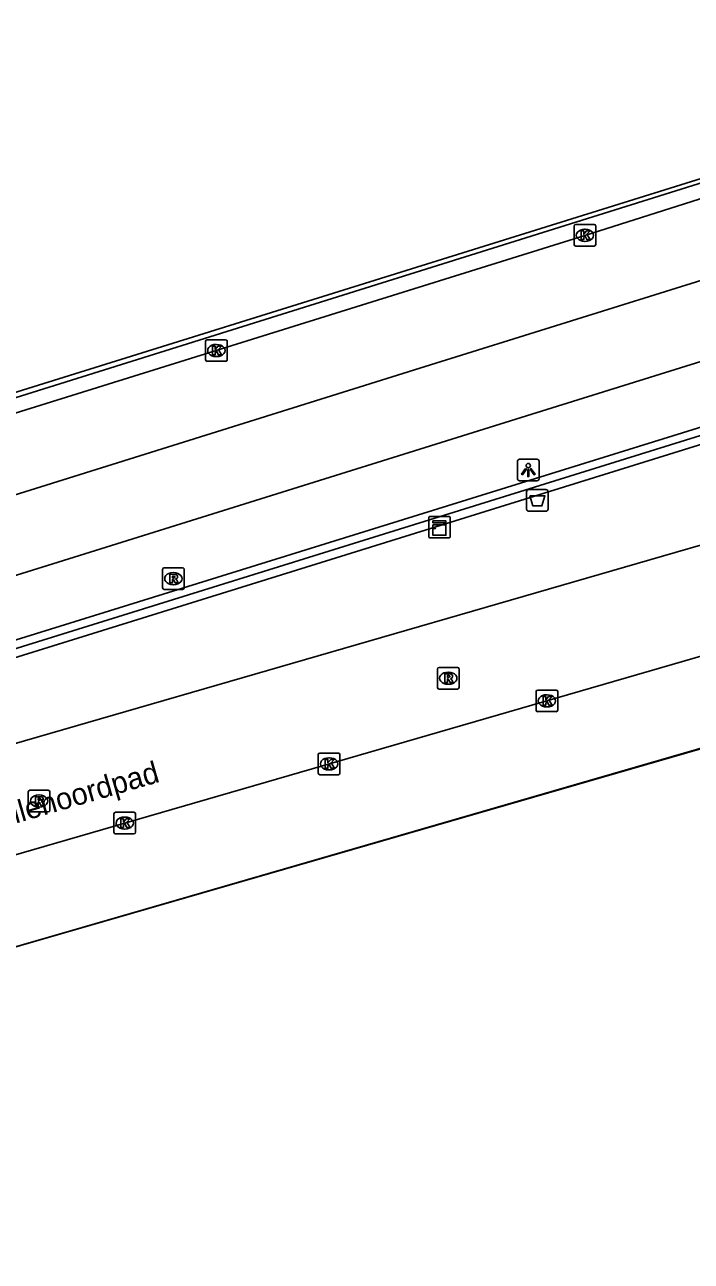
# Model space of a CAD drawing. Extents: x 160806 to 161707, y 383697 to 384148.
# Drawn here: x 161174.1 to 161204.9, y 383814.4 to 383871.5 of the extents above; entities that cross this region are included whole.
import ezdxf

# ---------------------------------------------------------------- set-up
doc = ezdxf.new("R2010")
doc.units = 0
for name, color, linetype in [('IMGEO_Afvalbak', 7, 'Continuous'), ('IMGEO_Fietspad_open', 7, 'Continuous'), ('IMGEO_Hek', 7, 'Continuous'), ('IMGEO_Kast', 7, 'Continuous'), ('IMGEO_Kolk', 7, 'Continuous'), ('IMGEO_Lichtpunt', 7, 'Continuous'), ('IMGEO_Muur', 7, 'Continuous'), ('IMGEO_Openbare_ruimte_label', 7, 'Continuous'), ('IMGEO_OVBaan_gesloten', 7, 'Continuous'), ('IMGEO_Pand', 7, 'Continuous'), ('IMGEO_Pand_overbouw', 7, 'Continuous'), ('IMGEO_Rioolput', 7, 'Continuous'), ('IMGEO_Voetpad_open', 7, 'Continuous')]:
    doc.layers.add(name, color=color, linetype=linetype)

msp = doc.modelspace()

# ---------------------------------------------------------------- linework, layer by layer
at = {"layer": 'IMGEO_Afvalbak'}
for p, q in [((161197.301, 383849.162), (161197.301, 383849.962)), ((161197.301, 383849.962), (161197.301, 383849.162)), ((161197.401, 383850.062), (161198.191, 383850.062)), ((161198.191, 383850.062), (161197.401, 383850.062)), ((161198.291, 383849.962), (161198.291, 383849.162)), ((161198.291, 383849.162), (161198.291, 383849.962)), ((161198.191, 383849.062), (161197.401, 383849.062)), ((161197.401, 383849.062), (161198.191, 383849.062))]:
    msp.add_line(p, q, dxfattribs=at)
msp.add_lwpolyline([(161197.444, 383849.776), (161198.148, 383849.776), (161197.999, 383849.306), (161197.593, 383849.306), (161197.444, 383849.776)], dxfattribs=at)
for centre, start, end in [((161197.401, 383849.962), 90, 180), ((161197.401, 383849.962), 90, 180), ((161198.191, 383849.962), 0, 90), ((161198.191, 383849.962), 360, 90), ((161197.401, 383849.162), 180, 270), ((161197.401, 383849.162), 180, 270), ((161198.191, 383849.162), 270, 0), ((161198.191, 383849.162), 270, 0)]:
    msp.add_arc(centre, 0.1, start, end, dxfattribs=at)
at = {"layer": 'IMGEO_Fietspad_open'}
for points in [[(161233.944, 383854.997), (161230.53, 383854.241), (161222.537, 383852.474), (161163.411, 383835.363), (161161.786, 383834.896)], [(161159.382, 383829.051), (161223.387, 383847.584)]]:
    msp.add_lwpolyline(points, dxfattribs=at)
at = {"layer": 'IMGEO_Hek'}
msp.add_lwpolyline([(161215.707, 383880.868), (161206.505, 383864.592), (161170.587, 383853.341), (161164.694, 383851.495)], dxfattribs=at)
at = {"layer": 'IMGEO_Kast'}
for p, q in [((161192.845, 383848.824), (161193.686, 383848.824)), ((161193.686, 383848.824), (161192.845, 383848.824)), ((161192.77, 383847.899), (161192.77, 383848.74)), ((161192.77, 383848.74), (161192.77, 383847.899)), ((161193.77, 383848.749), (161193.77, 383847.908)), ((161193.77, 383847.908), (161193.77, 383848.749)), ((161193.695, 383847.824), (161192.854, 383847.824)), ((161192.854, 383847.824), (161193.695, 383847.824))]:
    msp.add_line(p, q, dxfattribs=at)
for points in [[(161192.965, 383848.614), (161193.565, 383848.614), (161193.565, 383848.529), (161192.965, 383848.529), (161192.965, 383848.614)], [(161192.965, 383848.439), (161193.565, 383848.439), (161193.565, 383847.95), (161192.965, 383847.95), (161192.965, 383848.439)]]:
    msp.add_lwpolyline(points, dxfattribs=at)
msp.add_circle((161193.049, 383848.288), 0.0377, dxfattribs=at)
for centre, start, end in [((161192.848, 383848.746), 92.4484, 184.2845), ((161192.848, 383848.746), 92.4484, 184.2845), ((161193.692, 383848.746), 2.4484, 94.2845), ((161193.692, 383848.746), 2.4484, 94.2845), ((161192.848, 383847.902), 182.4484, 274.2845), ((161192.848, 383847.902), 182.4484, 274.2845), ((161193.692, 383847.902), 272.4484, 4.2845), ((161193.692, 383847.902), 272.4484, 4.2845)]:
    msp.add_arc(centre, 0.0779, start, end, dxfattribs=at)
at = {"layer": 'IMGEO_Kolk'}
for p, q in [((161199.494, 383861.384), (161199.494, 383862.236)), ((161199.569, 383862.31), (161200.421, 383862.31)), ((161199.982, 383862.09), (161200.007, 383862.09)), ((161200.495, 383862.236), (161200.495, 383861.384)), ((161200.005, 383861.53), (161199.98, 383861.53)), ((161200.421, 383861.31), (161199.569, 383861.31)), ((161182.451, 383856.061), (161182.451, 383856.913)), ((161182.526, 383856.987), (161183.378, 383856.987)), ((161183.452, 383856.913), (161183.452, 383856.061)), ((161182.939, 383856.767), (161182.964, 383856.767)), ((161183.378, 383855.987), (161182.526, 383855.987)), ((161182.962, 383856.207), (161182.937, 383856.207)), ((161197.737, 383839.872), (161197.737, 383840.724)), ((161197.812, 383840.798), (161198.664, 383840.798)), ((161198.225, 383840.578), (161198.25, 383840.578)), ((161198.738, 383840.724), (161198.738, 383839.872)), ((161198.664, 383839.798), (161197.812, 383839.798)), ((161198.248, 383840.018), (161198.223, 383840.018)), ((161187.666, 383836.959), (161187.666, 383837.811)), ((161187.741, 383837.885), (161188.593, 383837.885)), ((161188.154, 383837.665), (161188.179, 383837.665)), ((161188.667, 383837.811), (161188.667, 383836.959)), ((161188.593, 383836.885), (161187.741, 383836.885)), ((161188.177, 383837.105), (161188.152, 383837.105)), ((161178.288, 383835.15), (161179.14, 383835.15)), ((161178.213, 383834.224), (161178.213, 383835.076)), ((161178.701, 383834.93), (161178.726, 383834.93)), ((161179.214, 383835.076), (161179.214, 383834.224)), ((161179.14, 383834.15), (161178.288, 383834.15)), ((161178.724, 383834.37), (161178.699, 383834.37))]:
    msp.add_line(p, q, dxfattribs=at)
for points in [[(161199.494, 383861.384), (161199.494, 383862.236)], [(161199.569, 383862.31), (161200.421, 383862.31)], [(161199.815, 383862.01), (161199.938, 383862.01), (161199.938, 383861.859), (161200.068, 383862.01), (161200.232, 383862.01), (161200.086, 383861.859), (161200.239, 383861.61), (161200.087, 383861.61), (161200.002, 383861.774), (161199.938, 383861.707), (161199.938, 383861.61), (161199.815, 383861.61), (161199.815, 383862.01)], [(161200.495, 383862.236), (161200.495, 383861.384)], [(161200.421, 383861.31), (161199.569, 383861.31)], [(161182.451, 383856.061), (161182.451, 383856.913)], [(161182.526, 383856.987), (161183.378, 383856.987)], [(161183.452, 383856.913), (161183.452, 383856.061)], [(161182.772, 383856.687), (161182.895, 383856.687), (161182.895, 383856.536), (161183.025, 383856.687), (161183.189, 383856.687), (161183.043, 383856.536), (161183.196, 383856.287), (161183.044, 383856.287), (161182.959, 383856.451), (161182.895, 383856.384), (161182.895, 383856.287), (161182.772, 383856.287), (161182.772, 383856.687)], [(161183.378, 383855.987), (161182.526, 383855.987)], [(161197.737, 383839.872), (161197.737, 383840.724)], [(161197.812, 383840.798), (161198.664, 383840.798)], [(161198.058, 383840.498), (161198.181, 383840.498), (161198.181, 383840.347), (161198.311, 383840.498), (161198.475, 383840.498), (161198.329, 383840.347), (161198.482, 383840.098), (161198.33, 383840.098), (161198.245, 383840.262), (161198.181, 383840.195), (161198.181, 383840.098), (161198.058, 383840.098), (161198.058, 383840.498)], [(161198.738, 383840.724), (161198.738, 383839.872)], [(161198.664, 383839.798), (161197.812, 383839.798)], [(161187.666, 383836.959), (161187.666, 383837.811)], [(161187.741, 383837.885), (161188.593, 383837.885)], [(161187.987, 383837.585), (161188.11, 383837.585), (161188.11, 383837.434), (161188.24, 383837.585), (161188.404, 383837.585), (161188.258, 383837.434), (161188.411, 383837.185), (161188.259, 383837.185), (161188.174, 383837.349), (161188.11, 383837.282), (161188.11, 383837.185), (161187.987, 383837.185), (161187.987, 383837.585)], [(161188.667, 383837.811), (161188.667, 383836.959)], [(161188.593, 383836.885), (161187.741, 383836.885)], [(161178.288, 383835.15), (161179.14, 383835.15)], [(161178.213, 383834.224), (161178.213, 383835.076)], [(161178.534, 383834.85), (161178.657, 383834.85), (161178.657, 383834.699), (161178.787, 383834.85), (161178.951, 383834.85), (161178.805, 383834.699), (161178.958, 383834.45), (161178.806, 383834.45), (161178.721, 383834.614), (161178.657, 383834.547), (161178.657, 383834.45), (161178.534, 383834.45), (161178.534, 383834.85)], [(161179.214, 383835.076), (161179.214, 383834.224)], [(161179.14, 383834.15), (161178.288, 383834.15)]]:
    msp.add_lwpolyline(points, dxfattribs=at)
for centre, start, end in [((161199.571, 383862.234), 91.552, 178.448), ((161199.571, 383862.234), 91.552, 178.448), ((161200.419, 383862.234), 1.552, 88.448), ((161200.419, 383862.234), 1.552, 88.448), ((161199.571, 383861.386), 181.552, 268.448), ((161199.571, 383861.386), 181.552, 268.448), ((161200.419, 383861.386), 271.552, 358.448), ((161200.419, 383861.386), 271.552, 358.448), ((161182.528, 383856.911), 91.552, 178.448), ((161182.528, 383856.911), 91.552, 178.448), ((161183.376, 383856.911), 1.552, 88.448), ((161183.376, 383856.911), 1.552, 88.448), ((161182.528, 383856.063), 181.552, 268.448), ((161182.528, 383856.063), 181.552, 268.448), ((161183.376, 383856.063), 271.552, 358.448), ((161183.376, 383856.063), 271.552, 358.448), ((161197.814, 383840.722), 91.552, 178.448), ((161197.814, 383840.722), 91.552, 178.448), ((161198.662, 383840.722), 1.552, 88.448), ((161198.662, 383840.722), 1.552, 88.448), ((161197.814, 383839.874), 181.552, 268.448), ((161197.814, 383839.874), 181.552, 268.448), ((161198.662, 383839.874), 271.552, 358.448), ((161198.662, 383839.874), 271.552, 358.448), ((161187.743, 383837.809), 91.552, 178.448), ((161187.743, 383837.809), 91.552, 178.448), ((161188.591, 383837.809), 1.552, 88.448), ((161188.591, 383837.809), 1.552, 88.448), ((161187.743, 383836.961), 181.552, 268.448), ((161187.743, 383836.961), 181.552, 268.448), ((161188.591, 383836.961), 271.552, 358.448), ((161188.591, 383836.961), 271.552, 358.448), ((161178.29, 383835.074), 91.552, 178.448), ((161178.29, 383835.074), 91.552, 178.448), ((161179.138, 383835.074), 1.552, 88.448), ((161179.138, 383835.074), 1.552, 88.448), ((161178.29, 383834.226), 181.552, 268.448), ((161178.29, 383834.226), 181.552, 268.448), ((161179.138, 383834.226), 271.552, 358.448), ((161179.138, 383834.226), 271.552, 358.448)]:
    msp.add_arc(centre, 0.0765, start, end, dxfattribs=at)
for centre, major_axis, ratio, start_param, end_param in [((161199.981, 383861.81), (-0.387, 0.002), 0.722429, 4.712389, 7.853982), ((161200.006, 383861.81), (-0.39, 0.002), 0.717154, 1.570796, 4.712389), ((161182.938, 383856.487), (-0.387, 0.002), 0.722429, 4.712389, 7.853982), ((161182.963, 383856.487), (-0.39, 0.002), 0.717154, 1.570796, 4.712389), ((161198.224, 383840.298), (-0.387, 0.002), 0.722429, 4.712389, 7.853982), ((161198.249, 383840.298), (-0.39, 0.002), 0.717154, 1.570796, 4.712389), ((161188.153, 383837.385), (-0.387, 0.002), 0.722429, 4.712389, 7.853982), ((161188.178, 383837.385), (-0.39, 0.002), 0.717154, 1.570796, 4.712389), ((161178.7, 383834.65), (-0.387, 0.002), 0.722429, 4.712389, 7.853982), ((161178.725, 383834.65), (-0.39, 0.002), 0.717154, 1.570796, 4.712389)]:
    msp.add_ellipse(centre, major_axis=major_axis, ratio=ratio, start_param=start_param, end_param=end_param, dxfattribs=at)
at = {"layer": 'IMGEO_Lichtpunt'}
for p, q in [((161196.876, 383851.369), (161196.876, 383850.562)), ((161196.876, 383851.369), (161196.876, 383850.562)), ((161197.778, 383851.464), (161196.97, 383851.464)), ((161197.778, 383851.464), (161196.97, 383851.464)), ((161197.872, 383850.562), (161197.872, 383851.369)), ((161197.872, 383850.562), (161197.872, 383851.369)), ((161196.97, 383850.468), (161197.778, 383850.468)), ((161196.97, 383850.468), (161197.778, 383850.468))]:
    msp.add_line(p, q, dxfattribs=at)
for points in [[(161197.25, 383851.033), (161197.289, 383851.005), (161197.101, 383850.743), (161197.063, 383850.77), (161197.25, 383851.033)], [(161197.352, 383850.985), (161197.399, 383850.985), (161197.399, 383850.663), (161197.352, 383850.663), (161197.352, 383850.985)], [(161197.462, 383851.005), (161197.5, 383851.032), (161197.687, 383850.77), (161197.648, 383850.742), (161197.462, 383851.005)]]:
    msp.add_lwpolyline(points, dxfattribs=at)
msp.add_circle((161197.375, 383851.167), 0.0994, dxfattribs=at)
for centre, start, end in [((161196.97, 383851.369), 90, 180), ((161196.97, 383851.369), 90, 180), ((161197.778, 383851.369), 0, 90), ((161197.778, 383851.369), 0, 90), ((161196.97, 383850.562), 180, 270), ((161196.97, 383850.562), 180, 270), ((161197.778, 383850.562), 270, 0), ((161197.778, 383850.562), 270, 360)]:
    msp.add_arc(centre, 0.0946, start, end, dxfattribs=at)
at = {"layer": 'IMGEO_Muur'}
for points in [[(161156.904, 383837.916), (161229.219, 383860.361), (161230.728, 383855.33)], [(161226.937, 383859.268), (161157.726, 383837.763)]]:
    msp.add_lwpolyline(points, dxfattribs=at)
at = {"layer": 'IMGEO_OVBaan_gesloten'}
for points in [[(161231.771, 383868.031), (161217.778, 383863.592), (161209.997, 383861.169), (161192.607, 383855.742), (161162.9, 383846.464), (161159.136, 383845.321), (161157.213, 383844.802), (161155.744, 383844.438), (161154.991, 383844.26)], [(161156.084, 383840.634), (161167.281, 383844.11), (161197.293, 383853.461), (161220.786, 383860.784), (161232.169, 383864.306)], [(161154.024, 383847.47), (161164.58, 383850.768), (161182.948, 383856.486), (161199.991, 383861.809), (161206.252, 383863.795)]]:
    msp.add_lwpolyline(points, dxfattribs=at)
at = {"layer": 'IMGEO_Pand'}
msp.add_lwpolyline([(161214.94, 383840.857), (161157.832, 383824.35)], dxfattribs=at)
at = {"layer": 'IMGEO_Pand_overbouw'}
msp.add_lwpolyline([(161244.397, 383752.352), (161218.72, 383841.978), (161097.833, 383806.973), (161123.797, 383717.365)], close=True, dxfattribs=at)
at = {"layer": 'IMGEO_Rioolput'}
for p, q in [((161180.463, 383845.519), (161180.463, 383846.371)), ((161180.538, 383846.445), (161181.39, 383846.445)), ((161180.951, 383846.225), (161180.976, 383846.225)), ((161181.464, 383846.371), (161181.464, 383845.519)), ((161181.39, 383845.445), (161180.538, 383845.445)), ((161180.974, 383845.665), (161180.949, 383845.665)), ((161193.177, 383840.917), (161193.177, 383841.769)), ((161193.252, 383841.843), (161194.104, 383841.843)), ((161193.665, 383841.623), (161193.69, 383841.623)), ((161194.178, 383841.769), (161194.178, 383840.917)), ((161194.104, 383840.843), (161193.252, 383840.843)), ((161193.688, 383841.063), (161193.663, 383841.063)), ((161174.251, 383835.242), (161174.251, 383836.094)), ((161174.326, 383836.168), (161175.178, 383836.168)), ((161174.739, 383835.948), (161174.764, 383835.948)), ((161175.252, 383836.094), (161175.252, 383835.242)), ((161175.178, 383835.168), (161174.326, 383835.168)), ((161174.762, 383835.388), (161174.737, 383835.388))]:
    msp.add_line(p, q, dxfattribs=at)
for points in [[(161180.463, 383845.519), (161180.463, 383846.371)], [(161180.538, 383846.445), (161181.39, 383846.445)], [(161181.052, 383846.143), (161180.8, 383846.145), (161180.8, 383845.745)], [(161180.978, 383846.064), (161180.924, 383846.064), (161180.924, 383845.983)], [(161180.924, 383845.983), (161180.976, 383845.983)], [(161181.464, 383846.371), (161181.464, 383845.519)], [(161181.39, 383845.445), (161180.538, 383845.445)], [(161180.8, 383845.745), (161180.924, 383845.745), (161180.924, 383845.907), (161180.935, 383845.907)], [(161180.982, 383845.878), (161181.053, 383845.745), (161181.193, 383845.745), (161181.128, 383845.871)], [(161193.177, 383840.917), (161193.177, 383841.769)], [(161193.252, 383841.843), (161194.104, 383841.843)], [(161193.766, 383841.541), (161193.514, 383841.543), (161193.514, 383841.143)], [(161193.692, 383841.462), (161193.638, 383841.462), (161193.638, 383841.381)], [(161194.178, 383841.769), (161194.178, 383840.917)], [(161194.104, 383840.843), (161193.252, 383840.843)], [(161193.514, 383841.143), (161193.638, 383841.143), (161193.638, 383841.305), (161193.649, 383841.305)], [(161193.638, 383841.381), (161193.69, 383841.381)], [(161193.696, 383841.276), (161193.767, 383841.143), (161193.907, 383841.143), (161193.842, 383841.269)], [(161174.251, 383835.242), (161174.251, 383836.094)], [(161174.326, 383836.168), (161175.178, 383836.168)], [(161174.84, 383835.866), (161174.588, 383835.868), (161174.588, 383835.468)], [(161174.766, 383835.787), (161174.712, 383835.787), (161174.712, 383835.706)], [(161174.712, 383835.706), (161174.764, 383835.706)], [(161175.252, 383836.094), (161175.252, 383835.242)], [(161175.178, 383835.168), (161174.326, 383835.168)], [(161174.588, 383835.468), (161174.712, 383835.468), (161174.712, 383835.63), (161174.723, 383835.63)], [(161174.77, 383835.601), (161174.841, 383835.468), (161174.981, 383835.468), (161174.916, 383835.594)]]:
    msp.add_lwpolyline(points, dxfattribs=at)
for centre, radius, start, end in [((161180.54, 383846.369), 0.0765, 91.552, 178.448), ((161180.54, 383846.369), 0.0765, 91.552, 178.448), ((161180.96, 383846.172), 0.19, 274.7715, 282.9687), ((161180.984, 383845.968), 0.0964, 77.0061, 93.1865), ((161180.998, 383846.025), 0.0378, 276.6634, 79.6772), ((161181.051, 383846.033), 0.109, 350.3612, 89.416), ((161181.049, 383846.033), 0.112, 277.5842, 350.9817), ((161181.388, 383846.369), 0.0765, 1.552, 88.448), ((161181.388, 383846.369), 0.0765, 1.552, 88.448), ((161180.54, 383845.521), 0.0765, 181.552, 268.448), ((161180.54, 383845.521), 0.0765, 181.552, 268.448), ((161180.934, 383845.854), 0.0533, 26.0293, 88.6989), ((161181.033, 383845.818), 0.108, 29.5134, 73.7905), ((161181.388, 383845.521), 0.0765, 271.552, 358.448), ((161181.388, 383845.521), 0.0765, 271.552, 358.448), ((161193.254, 383841.767), 0.0765, 91.552, 178.448), ((161193.254, 383841.767), 0.0765, 91.552, 178.448), ((161193.698, 383841.366), 0.0964, 77.0061, 93.1865), ((161193.712, 383841.423), 0.0378, 276.6634, 79.6772), ((161193.765, 383841.431), 0.109, 350.3612, 89.416), ((161193.763, 383841.431), 0.112, 277.5842, 350.9817), ((161194.102, 383841.767), 0.0765, 1.552, 88.448), ((161194.102, 383841.767), 0.0765, 1.552, 88.448), ((161193.254, 383840.919), 0.0765, 181.552, 268.448), ((161193.254, 383840.919), 0.0765, 181.552, 268.448), ((161193.648, 383841.252), 0.0533, 26.0293, 88.6989), ((161193.674, 383841.57), 0.19, 274.7715, 282.9687), ((161193.747, 383841.216), 0.108, 29.5134, 73.7905), ((161194.102, 383840.919), 0.0765, 271.552, 358.448), ((161194.102, 383840.919), 0.0765, 271.552, 358.448), ((161174.328, 383836.092), 0.0765, 91.552, 178.448), ((161174.328, 383836.092), 0.0765, 91.552, 178.448), ((161174.748, 383835.895), 0.19, 274.7715, 282.9687), ((161174.772, 383835.691), 0.0964, 77.0061, 93.1865), ((161174.786, 383835.748), 0.0378, 276.6634, 79.6772), ((161174.839, 383835.756), 0.109, 350.3612, 89.416), ((161174.837, 383835.756), 0.112, 277.5842, 350.9817), ((161175.176, 383836.092), 0.0765, 1.552, 88.448), ((161175.176, 383836.092), 0.0765, 1.552, 88.448), ((161174.328, 383835.244), 0.0765, 181.552, 268.448), ((161174.328, 383835.244), 0.0765, 181.552, 268.448), ((161174.722, 383835.577), 0.0533, 26.0293, 88.6989), ((161174.821, 383835.541), 0.108, 29.5134, 73.7905), ((161175.176, 383835.244), 0.0765, 271.552, 358.448), ((161175.176, 383835.244), 0.0765, 271.552, 358.448)]:
    msp.add_arc(centre, radius, start, end, dxfattribs=at)
for centre, major_axis, ratio, start_param, end_param in [((161180.95, 383845.945), (-0.387, 0.002), 0.722429, 4.712389, 7.853982), ((161180.975, 383845.945), (-0.39, 0.002), 0.717154, 1.570796, 4.712389), ((161193.664, 383841.343), (-0.387, 0.002), 0.722429, 4.712389, 7.853982), ((161193.689, 383841.343), (-0.39, 0.002), 0.717154, 1.570796, 4.712389), ((161174.738, 383835.668), (-0.387, 0.002), 0.722429, 4.712389, 7.853982), ((161174.763, 383835.668), (-0.39, 0.002), 0.717154, 1.570796, 4.712389)]:
    msp.add_ellipse(centre, major_axis=major_axis, ratio=ratio, start_param=start_param, end_param=end_param, dxfattribs=at)
at = {"layer": 'IMGEO_Voetpad_open'}
for points in [[(161205.617, 383864.517), (161152.666, 383848.01)], [(161160.918, 383838.336), (161227.057, 383858.887), (161226.937, 383859.268)]]:
    msp.add_lwpolyline(points, dxfattribs=at)

# ---------------------------------------------------------------- texts
at = {"layer": 'IMGEO_Openbare_ruimte_label'}
msp.add_text('Fellenoordpad', height=1, rotation=16.1342, dxfattribs=at).set_placement((161172.17, 383834.19))

doc.saveas('drawing.dxf')
